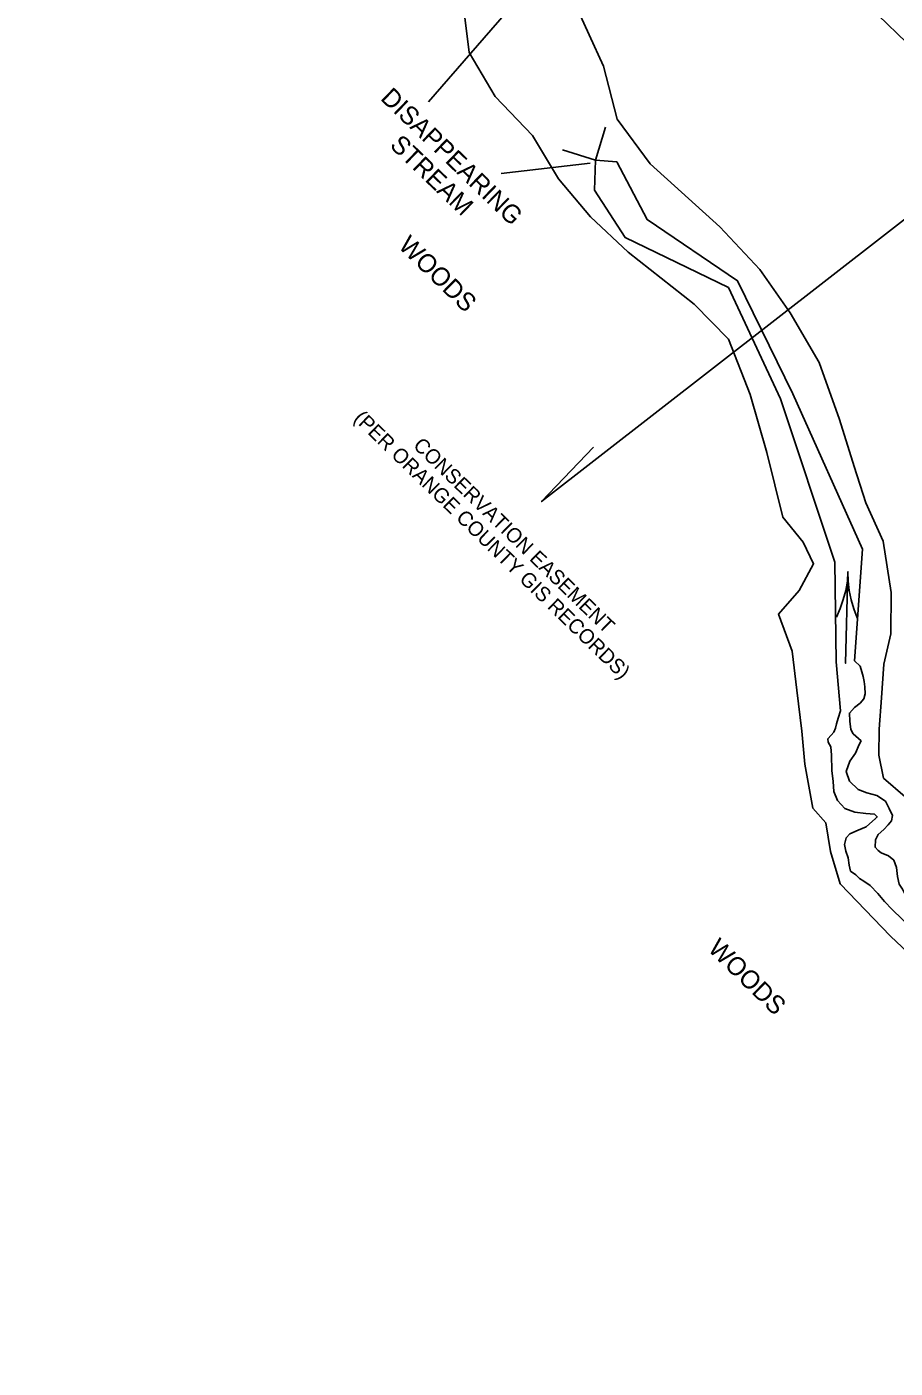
# Model space of a CAD drawing. Extents: x 1977096 to 1980486, y 845025 to 848427.
# Drawn here: x 1978965.2 to 1979154.9, y 845950 to 846243.1 of the extents above; entities that cross this region are included whole.
import ezdxf

# ---------------------------------------------------------------- set-up
doc = ezdxf.new("R2010")
doc.units = 0
for name, color, linetype in [('Exist Hydro Disappearing Stream CELL', 7, 'Continuous'), ('Exist Hydro Disappearing Stream Text', 7, 'Continuous'), ('Exist Hydro Jurisdictional Stream or Body of Water', 7, 'Continuous'), ('Exist Hydro River Flow Arrow CELL', 7, 'Continuous'), ('Exist Property Same Owner Line CELL', 7, 'Continuous'), ('Exist Right of Way Easement Line Text', 7, 'Continuous'), ('Exist Right of Way Line', 7, 'Continuous'), ('Exist Vegetation Woods Line', 7, 'Continuous'), ('Exist Vegetation Woods Line Text', 7, 'Continuous')]:
    doc.layers.add(name, color=color, linetype=linetype)

msp = doc.modelspace()

# ---------------------------------------------------------------- linework, layer by layer
at = {"layer": 'Exist Hydro Disappearing Stream CELL'}
for q in [(1979091.63, 846221.23), (1979082.22, 846216.23), (1979089.42, 846214.02)]:
    msp.add_line((1979089.42, 846214.02), q, dxfattribs=at)
at = {"layer": 'Exist Hydro Disappearing Stream Text'}
for p, q in [((1979072.98, 846249.78), (1979052.99, 846226.75)), ((1979088.28, 846213.31), (1979068.85, 846211.05))]:
    msp.add_line(p, q, dxfattribs=at)
at = {"layer": 'Exist Hydro Jurisdictional Stream or Body of Water'}
for points in [[(1979089.41, 846214.01), (1979089.22, 846207.43), (1979095.89, 846197.09), (1979118.48, 846186.13), (1979129.85, 846161.87)], [(1979089.41, 846214.01), (1979089.41, 846214.01)], [(1979089.41, 846214.01), (1979094.07, 846213.59), (1979100.73, 846201.01), (1979120.48, 846187.63), (1979132.58, 846162.92)], [(1979129.85, 846161.87), (1979141.74, 846126.15), (1979141.99, 846104.34)], [(1979132.58, 846162.92), (1979147.78, 846128.99), (1979146.01, 846104.59)], [(1979146.01, 846104.59), (1979147.22, 846103.44), (1979147.61, 846102.17), (1979147.91, 846101.18), (1979148.11, 846100.09), (1979148.31, 846098.89), (1979148.33, 846097.4), (1979148.03, 846096.26), (1979147.22, 846095.31), (1979146.02, 846094.43), (1979144.9, 846093.18), (1979145.01, 846091.39), (1979145.21, 846089.56), (1979145.74, 846088.65), (1979147.45, 846087.08), (1979147.03, 846086.3)], [(1979141.99, 846104.34), (1979142.97, 846093.66), (1979142.42, 846092.09), (1979142.09, 846090.83), (1979141.88, 846089.85), (1979141.48, 846088.98), (1979140.93, 846088.36), (1979140.2, 846087.52), (1979140.24, 846086.79), (1979140.87, 846085.77), (1979140.87, 846085.77)], [(1979140.87, 846085.77), (1979140.97, 846083.98), (1979141.1, 846080.61), (1979141.39, 846078.23), (1979141.49, 846076.04)], [(1979147.03, 846086.3), (1979146.27, 846084.4), (1979145.01, 846082.64), (1979144.19, 846080.43), (1979144.89, 846078.33), (1979146.82, 846076.5), (1979148.69, 846075.76), (1979150.93, 846075.14), (1979152.76, 846073.92), (1979153.56, 846072.35)], [(1979141.49, 846076.04), (1979142.27, 846074.1), (1979143.88, 846072.34), (1979146.1, 846071.49), (1979148.5, 846071.25), (1979150.37, 846071.09), (1979150.99, 846070.48), (1979150.64, 846070.14), (1979150.64, 846070.14)], [(1979153.56, 846072.35), (1979154.3, 846070.8), (1979154.09, 846069.65), (1979153.4, 846068.76), (1979153.4, 846068.76)], [(1979150.64, 846070.14), (1979148.57, 846068.29), (1979146.83, 846067.57), (1979144.99, 846066.76), (1979144.22, 846065.89), (1979143.87, 846064.49), (1979144.1, 846062.99), (1979144.62, 846061.52), (1979144.83, 846059.91), (1979145.14, 846058.65)], [(1979153.4, 846068.76), (1979152.43, 846067.75), (1979151.21, 846066.65), (1979150.57, 846065.45), (1979150.51, 846063.85), (1979151.19, 846063.12), (1979151.81, 846062.65)], [(1979151.81, 846062.65), (1979153.44, 846062), (1979154.6, 846061.02), (1979155.17, 846059.43), (1979155.44, 846057.5), (1979155.75, 846055.8), (1979156.5, 846054.7), (1979157.01, 846053.69), (1979157.6, 846052.3), (1979159.5, 846051.47), (1979161.77, 846051.56), (1979163.47, 846050.98), (1979164.73, 846049.44), (1979166.09, 846048.4), (1979168.23, 846048.57), (1979169.39, 846047.34), (1979170.89, 846045.72), (1979172.17, 846044.44), (1979172.83, 846043.26), (1979173.57, 846042.54), (1979174.36, 846041.94), (1979175.69, 846041.32), (1979175.69, 846041.32)], [(1979145.14, 846058.65), (1979145.14, 846058.65), (1979146.28, 846057.83), (1979147.09, 846057.06), (1979148.04, 846056.43), (1979149.44, 846055.53), (1979151.08, 846053.77), (1979152.57, 846051.98), (1979154.24, 846050.23), (1979156.43, 846048.14), (1979158.65, 846046.02), (1979160.89, 846043.77), (1979163.47, 846041.23), (1979165.75, 846039.39), (1979168.78, 846038.35), (1979170.62, 846037.72), (1979173.68, 846037.06)]]:
    msp.add_lwpolyline(points, dxfattribs=at)
at = {"layer": 'Exist Hydro River Flow Arrow CELL'}
msp.add_line((1979144.33, 846114.08), (1979144.33, 846114.08), dxfattribs=at)
msp.add_lwpolyline([(1979142.05, 846114.14), (1979142.88, 846116), (1979143.57, 846117.96), (1979144.1, 846119.98), (1979144.46, 846122.03), (1979144.59, 846124.07), (1979144.07, 846104.08), (1979144.59, 846124.07), (1979144.61, 846122.02), (1979144.87, 846119.96), (1979145.29, 846117.92), (1979145.88, 846115.92), (1979146.62, 846114.02)], dxfattribs=at)
at = {"layer": 'Exist Property Same Owner Line CELL'}
msp.add_lwpolyline([(1979292.37, 846303.36), (1979303.7, 846315.26), (1979077.67, 846139.38), (1979089, 846151.29)], dxfattribs=at)
at = {"layer": 'Exist Right of Way Line'}
msp.add_line((1978965.22, 846425.46), (1979456.98, 845950.04), dxfattribs=at)
at = {"layer": 'Exist Vegetation Woods Line'}
for points in [[(1979059.9, 846253.37), (1979061.86, 846237.5), (1979067.54, 846227.9), (1979075.7, 846219.39), (1979081.35, 846209.88), (1979088.37, 846201.64), (1979096.56, 846193.92), (1979111, 846182.53), (1979118.51, 846174.89), (1979123.21, 846162.76), (1979126.86, 846150.12), (1979130.38, 846135.95), (1979134.79, 846130.52), (1979137.08, 846125.78), (1979133.92, 846119.97), (1979129.45, 846114.77), (1979132.37, 846106.68), (1979133.4, 846098.15), (1979134.52, 846089.21), (1979135.2, 846082.02), (1979136.94, 846072.4)], [(1979152.36, 846078.92), (1979151.34, 846083.97), (1979151.37, 846089.67), (1979151.95, 846096.53), (1979152.44, 846103.84), (1979153.92, 846110.51), (1979154, 846119.51), (1979152.25, 846130.75), (1979148.51, 846139.09), (1979145.95, 846147.04), (1979142.75, 846157.33), (1979138.27, 846169.76), (1979131.94, 846180.62), (1979125.35, 846190.13), (1979116.62, 846199.42), (1979101.35, 846213.18), (1979094.16, 846222.94), (1979091.22, 846234.53), (1979084.91, 846248.23)], [(1979157.06, 846074.84), (1979152.36, 846078.92)], [(1979136.94, 846072.4), (1979139.76, 846069.18), (1979140.75, 846062.93), (1979142.9, 846055.9), (1979153.88, 846044.44), (1979160.12, 846038.5)]]:
    msp.add_lwpolyline(points, dxfattribs=at)

# ---------------------------------------------------------------- texts
at = {"layer": 'Exist Hydro Disappearing Stream Text'}
for s, p in [('DISAPPEARING', (1979042.28, 846227.3)), ('STREAM', (1979044.31, 846217.01))]:
    msp.add_text(s, height=4, rotation=316.0414, dxfattribs=at).set_placement(p)
at = {"layer": 'Exist Right of Way Easement Line Text'}
for s, p in [('(PER ORANGE COUNTY GIS RECORDS)', (1979036.43, 846157.32)), ('CONSERVATION EASEMENT', (1979049.41, 846151.41))]:
    msp.add_text(s, height=3.2, rotation=315.8475, dxfattribs=at).set_placement(p)
at = {"layer": 'Exist Vegetation Woods Line Text'}
for p in [(1979046.16, 846195.02), (1979113.77, 846041.43)]:
    msp.add_text('WOODS', height=4, rotation=315.6543, dxfattribs=at).set_placement(p)

doc.saveas('drawing.dxf')
